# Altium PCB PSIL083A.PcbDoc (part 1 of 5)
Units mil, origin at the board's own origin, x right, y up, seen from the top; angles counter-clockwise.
Board outline 8750 x 2700 mil, 4 copper layers (Top Layer, Signal Layer 1, Signal Layer 2, Bottom Layer), stack 61.2 mil thick; 463 components, 395 nets, 2267 pads, 745 vias.
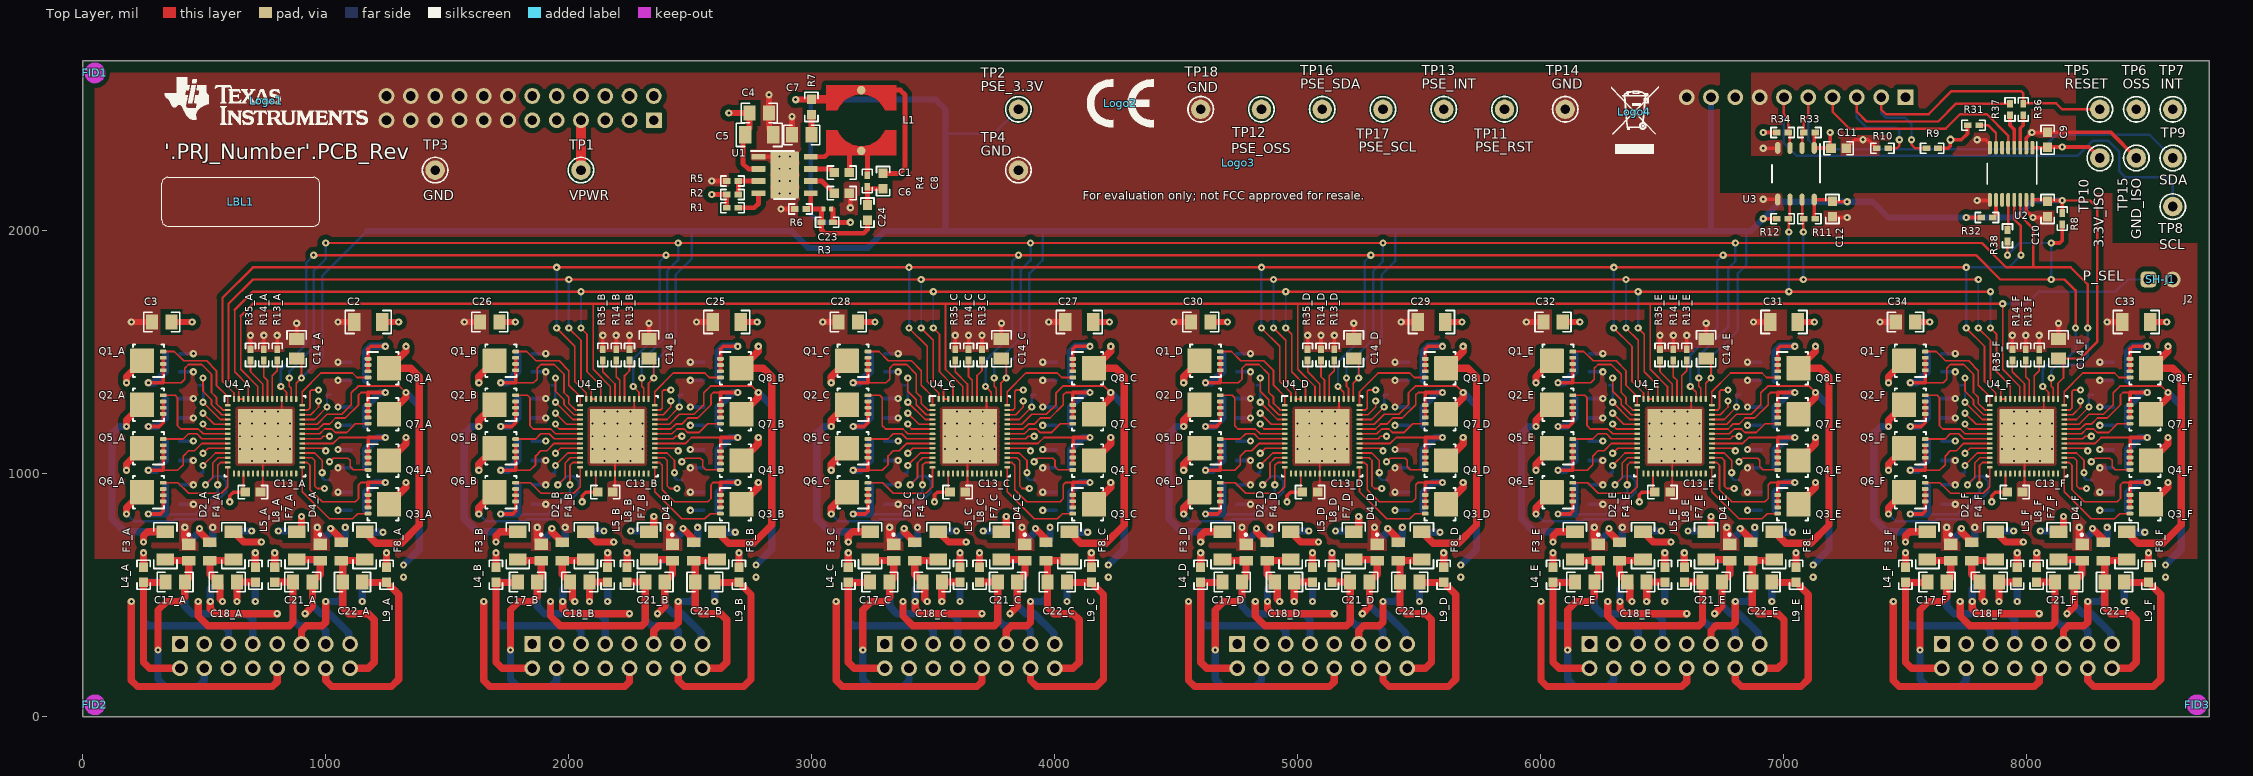
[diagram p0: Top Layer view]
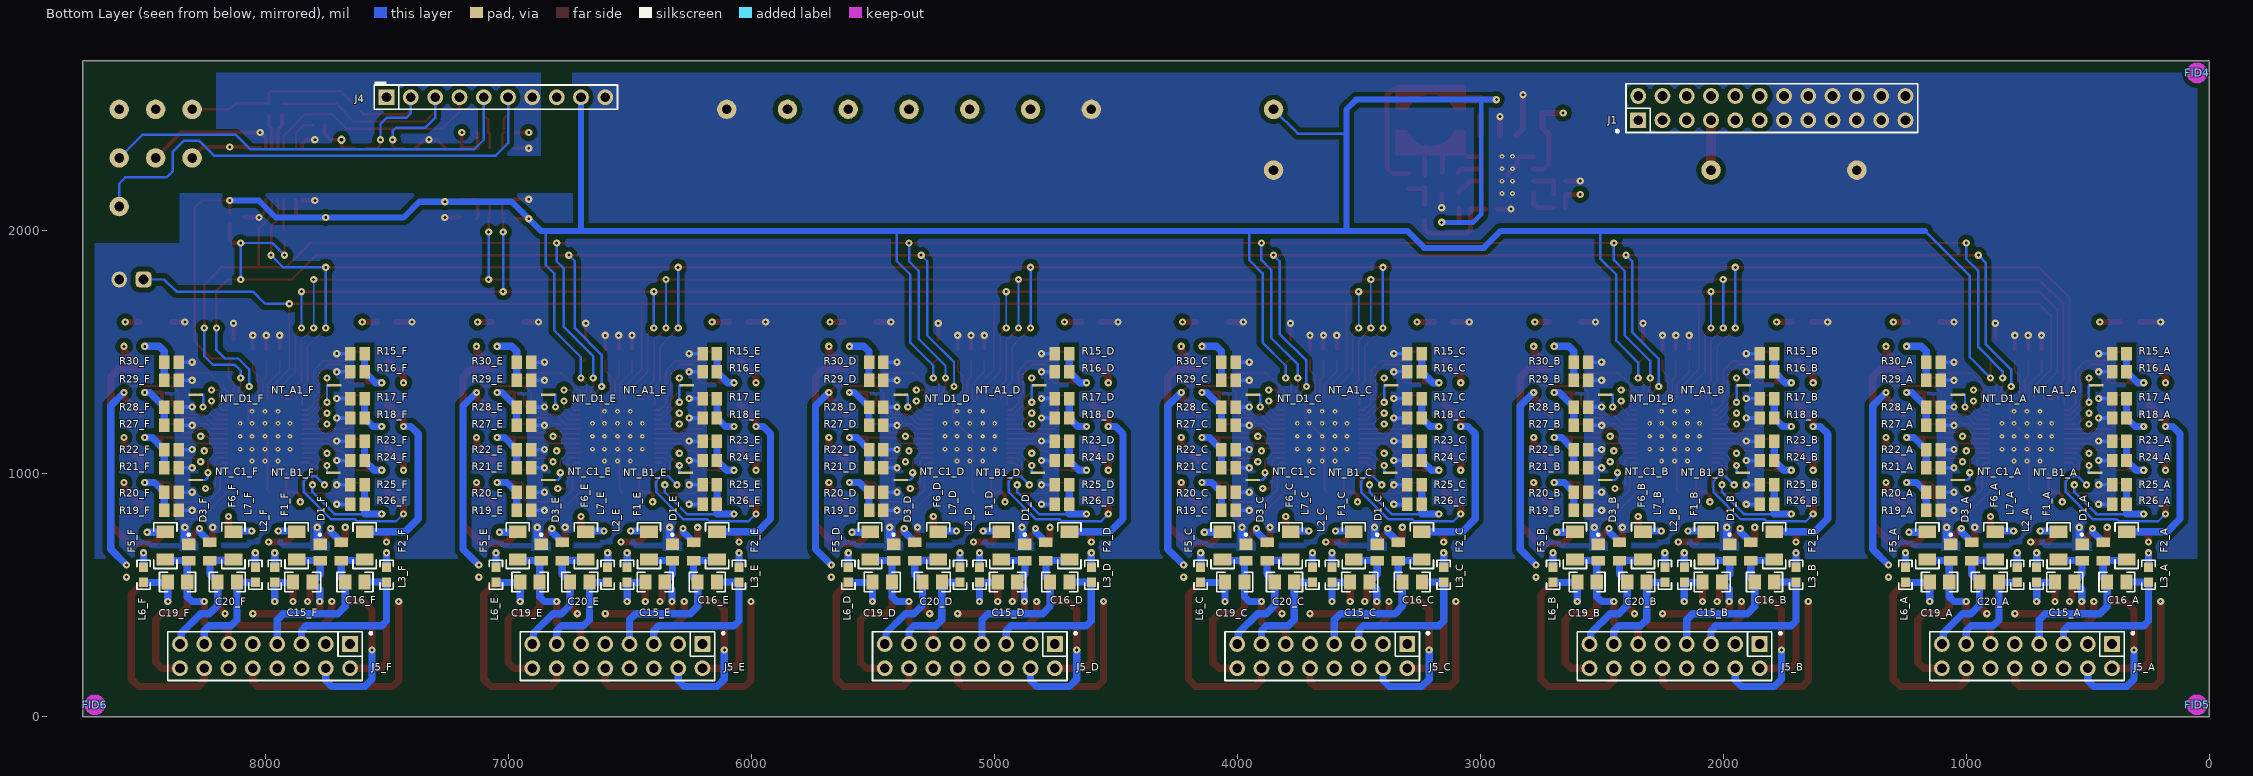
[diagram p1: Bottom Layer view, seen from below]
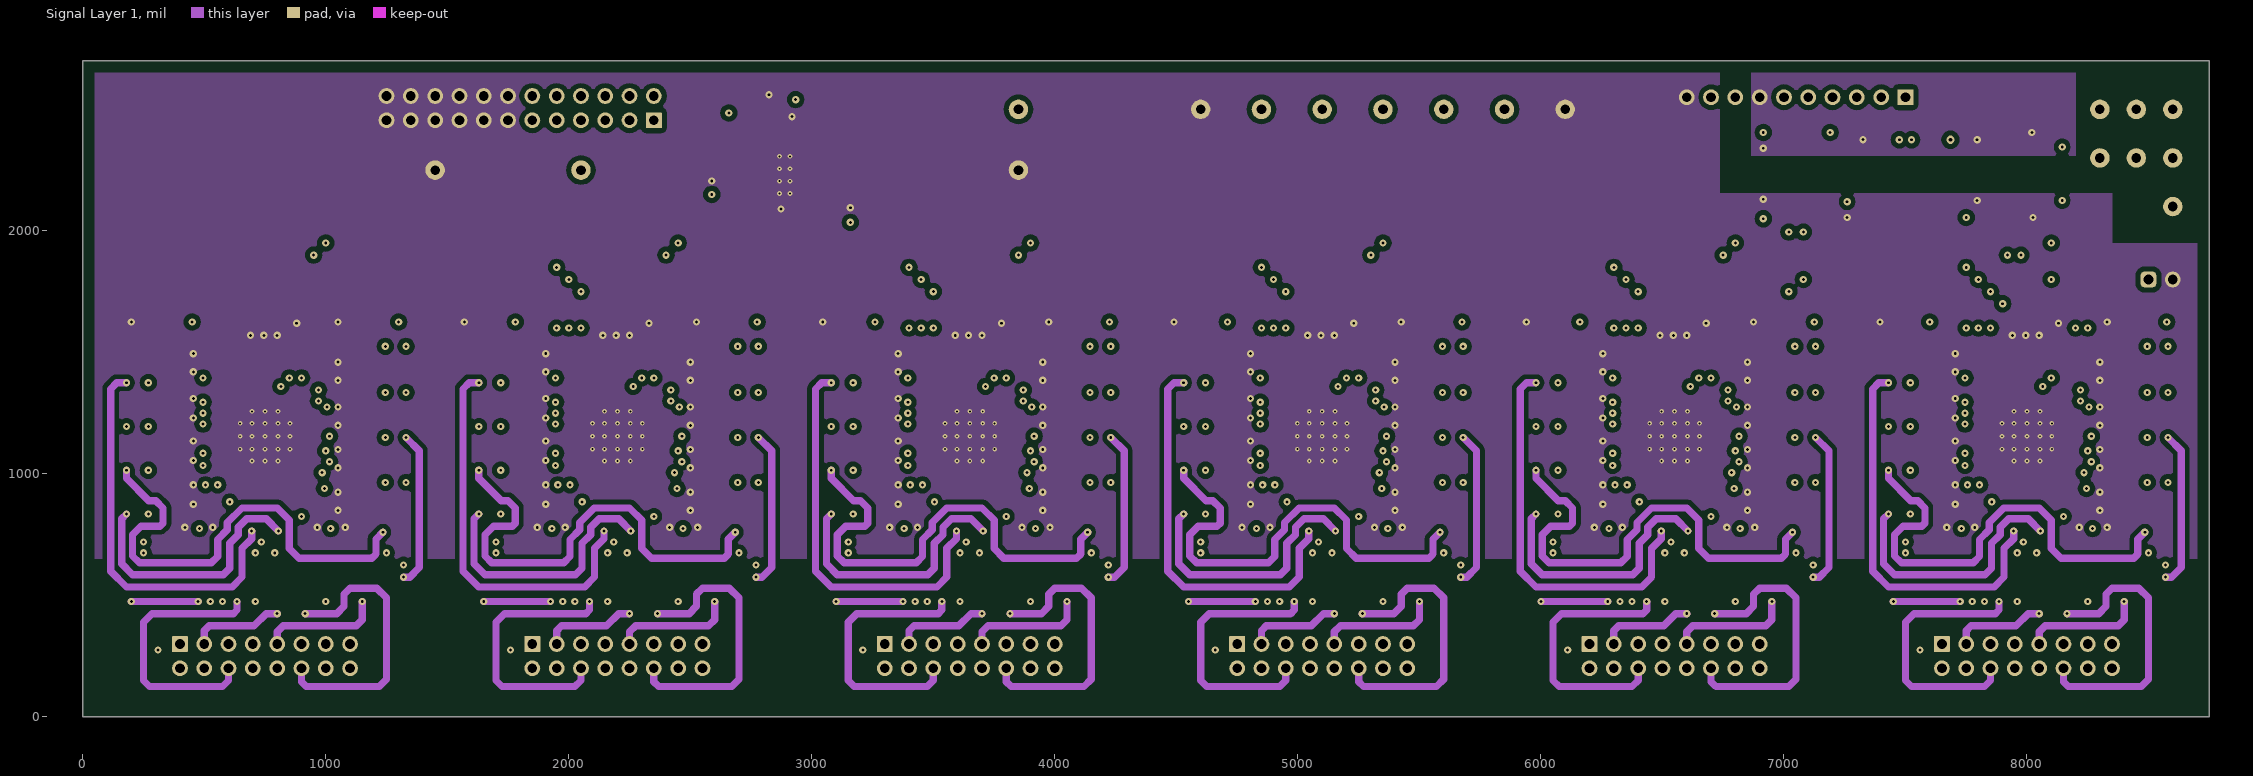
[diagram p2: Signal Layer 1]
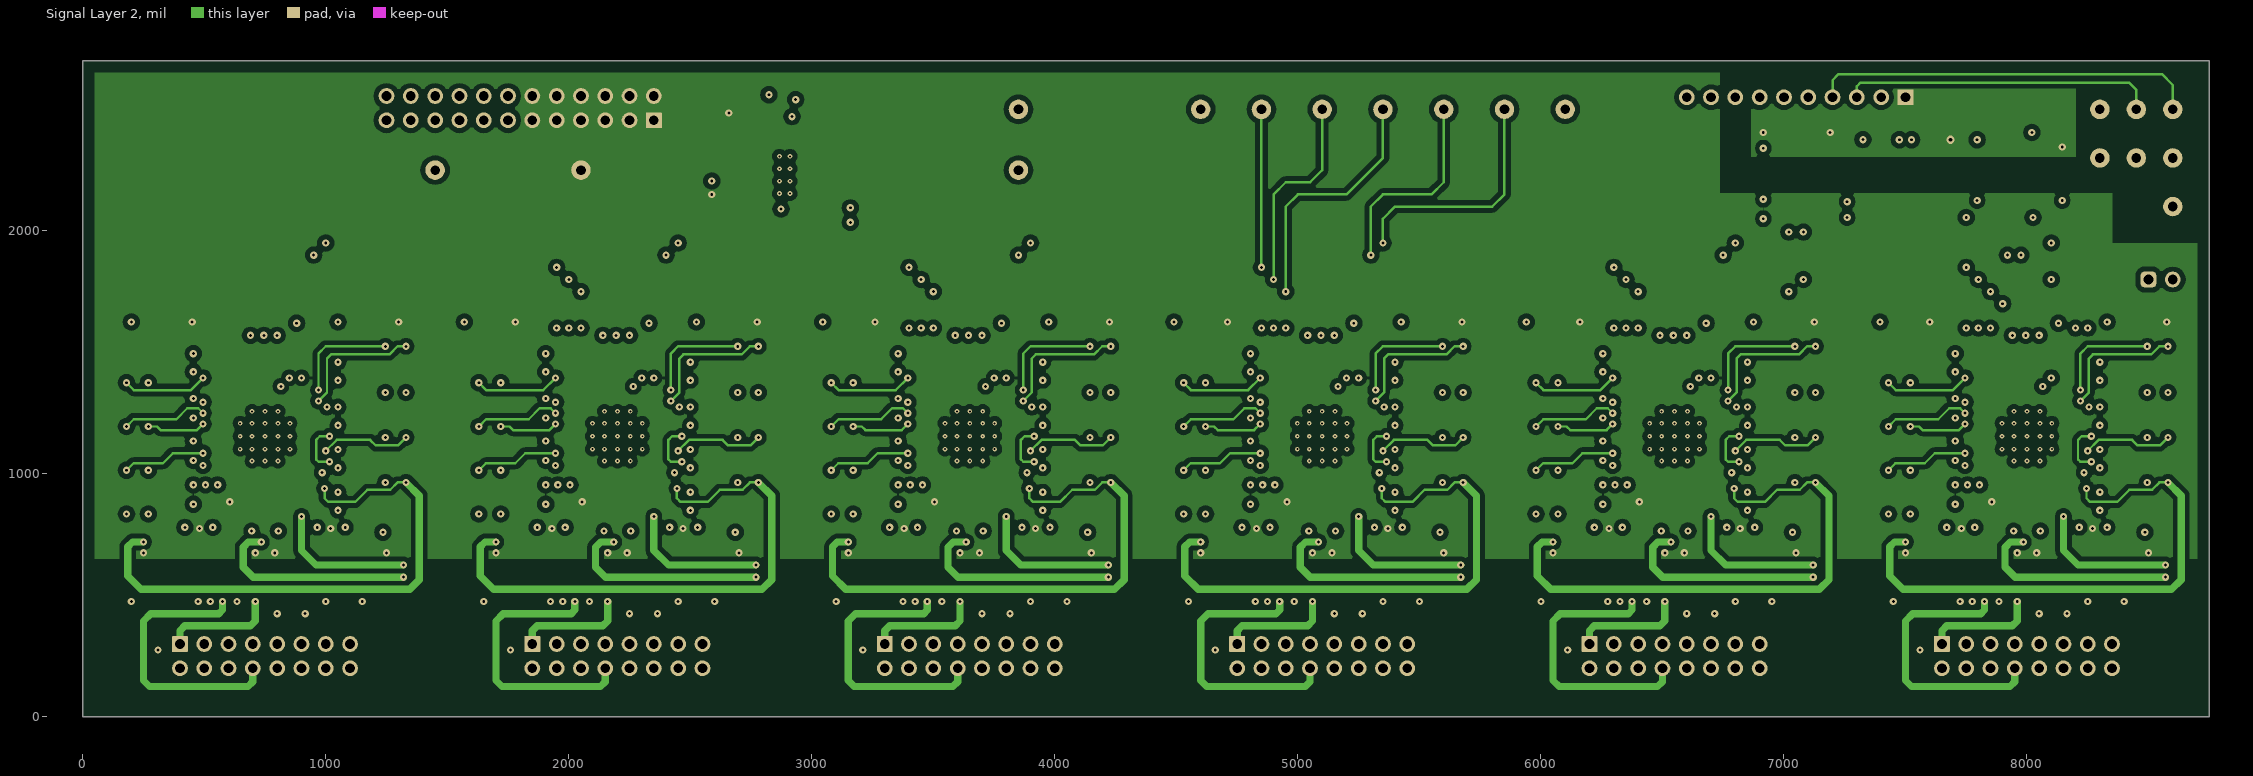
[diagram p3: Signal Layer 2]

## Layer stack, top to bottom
Top Solder: solder mask 0.4, Solder Resist, Dk 3.5
Top Layer: signal copper 2.8
Dielectric1: core 20, FR-4, Dk 4.2
Signal Layer 1: signal copper 2.8
Dielectric 2: prepreg 10, FR-4, Dk 4.2
Signal Layer 2: signal copper 2.8
Dielectric 3: core 20, FR-4, Dk 4.2
Bottom Layer: signal copper 2.8
Bottom Solder: solder mask 0.4, Solder Resist, Dk 3.5

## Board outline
0,0 8750,0 8750,2700 0,2700

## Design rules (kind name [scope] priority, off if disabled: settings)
AcuteAngle [All] p1: minimum=4.50000000000000E+0001 checktracksonly=FALSE
AssemblyTestPointUsage [All] p1: valid=2
BoardOutlineClearance BoardOutlineClearance_MountingHoles [OnCopper and InComponentClass('Mounting Holes')] p1: gap=40 ignorepadtopadclearanceinfootprint=FALSE
BoardOutlineClearance BoardOutlineClearance_Poly [OnCopper and IsPoly] p2: gap=25 ignorepadtopadclearanceinfootprint=FALSE
BoardOutlineClearance [OnCopper and Not InComponentClass('Logo') and not InComponentClass('FiducialMark') and not InRegion(1000,500,4000,800) and not InPoly] p3: gap=50 ignorepadtopadclearanceinfootprint=FALSE
Clearance Clearance_1 [InNamedPolygon('TOP_LAYER_PSE_S1_A_P004')] p1: gap=10 ignorepadtopadclearanceinfootprint=FALSE except(0: Arc-Hole Track-Hole SMDPad-Hole THPad-Hole Via-Hole Fill-Hole Poly-Hole Region-Hole Text-Hole)
Clearance Clearance_Keepouts [((IsTrack Or IsArc) And Not InPoly) And IsFree and IsKeepOut vs ((IsTrack Or IsArc) And Not InPoly) And IsFree and IsKeepOut] p2: gap=0 ignorepadtopadclearanceinfootprint=FALSE
Clearance Clearance_Poly [InPolygon] p3: gap=20 ignorepadtopadclearanceinfootprint=FALSE
Clearance Clearance_FiducialMark [IsKeepOut and InComponentClass('FiducialMark') vs IsPad and InComponentClass('FiducialMark')] p4: gap=0 ignorepadtopadclearanceinfootprint=FALSE
Clearance [All] p5: gap=7.87 ignorepadtopadclearanceinfootprint=FALSE except(0: Arc-Hole Track-Hole SMDPad-Hole THPad-Hole Via-Hole Fill-Hole Poly-Hole Region-Hole Text-Hole)
ComponentClearance ComponentClearance_MountingHoles_FiducialMarks [InComponentClass('Mounting Holes') vs InComponentClass('FiducialMark')] p1: gap=50 collisioncheckmode=3 verticalgap=10 showdistances=FALSE
ComponentClearance ComponentClearance_Shunt [InComponentClass('Header') vs InComponentClass('Shunt')] p2: gap=0 collisioncheckmode=3 verticalgap=0 showdistances=FALSE
ComponentClearance ComponentClearance_Logo [InComponentClass('Logo')] p3: gap=50 collisioncheckmode=3 verticalgap=10 showdistances=FALSE
ComponentClearance ComponentClearance_ScrewToNut [(HasFootprint('NY PMS 440 0025 PH')) vs (HasFootprint('Keystone_1902C'))] p4: gap=5 collisioncheckmode=3 verticalgap=10 showdistances=FALSE
ComponentClearance ComponentClearance_MountingHoles [InComponentClass('Mounting Holes')] p5: gap=250 collisioncheckmode=3 verticalgap=100000 showdistances=FALSE
ComponentClearance ComponentClearance_SmallPassives [HasFootprint('0201*') or HasFootprint('0402*') or HasFootprint('0508') or HasFootprint('0603*') or HasFootprint('0612') or HasFootprint('0805*') or HasFootprint('0815*') or HasFootprint('0830*') or HasFootprint('1206*') or HasFootprint('1210*') or HasFootprint('1808*') or HasFootprint('1812*') or HasFootprint('1825*') or HasFootprint('2010*') or HasFootprint('2220*') or HasFootprint('2225*') or HasFootprint('2512*') or HasFootprint('2728*') or HasFootprint('3518*') vs HasFootprint('0201*') or HasFootprint('0402*') or HasFootprint('0508') or HasFootprint('0603*') or HasFootprint('0612') or HasFootprint('0805*') or HasFootprint('0815*') or HasFootprint('0830*') or HasFootprint('1206*') or HasFootprint('1210*') or HasFootprint('1808*') or HasFootprint('1812*') or HasFootprint('1825*') or HasFootprint('2010*') or HasFootprint('2220*') or HasFootprint('2225*') or HasFootprint('2512*') or HasFootprint('2728*') or HasFootprint('3518*')] p6: gap=14.96 collisioncheckmode=3 verticalgap=10 showdistances=FALSE
ComponentClearance ComponentClearance_THtoSMT [IsThruComponent vs IsSMTComponent] p7: gap=40 collisioncheckmode=3 verticalgap=30 showdistances=FALSE
ComponentClearance ComponentClearance_THtoTH [IsThruComponent vs IsThruComponent] p8: gap=30 collisioncheckmode=3 verticalgap=30 showdistances=FALSE
ComponentClearance [All] p9: gap=30 collisioncheckmode=3 verticalgap=10 showdistances=FALSE
DiffPairsRouting [All] p1: maxlimit=100 minlimit=10 mostfreqgap=10 toplayer_minwidth=15 toplayer_maxwidth=15 toplayer_prefwidth=15 midlayer1_minwidth=15 midlayer1_maxwidth=15 midlayer1_prefwidth=15 midlayer2_minwidth=15 midlayer2_maxwidth=15 midlayer2_prefwidth=15 bottomlayer_minwidth=15 bottomlayer_maxwidth=15 bottomlayer_prefwidth=15 maxuncoupledlength=1000
FabricationTestPointUsage TestPointUsage [All] p1: valid=2 allowmultiple=FALSE
FabricationTestpoint Testpoint [All] p1: side=3 testpointundercomponent=TRUE minsize=40 maxsize=100 preferedsize=60 minholesize=0 maxholesize=40 preferedholesize=32 testpointgrid=1 allowsidetop=TRUE allowsidebottom=TRUE usegrid=TRUE gridtolerance=0.01
FanoutControl Fanout_LCC [IsLCC] p1: bgadir=Out bgaviamode=Centered fanoutstyle=Auto fanoutdirection=Alternating viagrid=1 // Fanout_LCC (Default Rule)
FanoutControl Fanout_BGA [IsBGA] p2: bgadir=Out bgaviamode=Centered fanoutstyle=Auto fanoutdirection=Alternating viagrid=1 // Fanout_BGA (Default Rule)
FanoutControl Fanout_Default [All] p4: bgadir=Out bgaviamode=Centered fanoutstyle=Auto fanoutdirection=Alternating viagrid=1 // Fanout_Default (Default Rule)
FanoutControl Fanout_Small [(CompPinCount < 5)] p5: bgadir=Out bgaviamode=Centered fanoutstyle=Auto fanoutdirection=OutThenIn viagrid=1 // Fanout_Small (Default Rule)
HoleSize [All] p1: absolutevalues=TRUE maxlimit=251 minlimit=7.87 maxpercent=80.000 minpercent=20.000
MinimumAnnularRing MinimumAnnularRing_ThermalPadVias [IsVia and InAnyComponent] p1: minimumring=5.91
MinimumAnnularRing [All] p2: minimumring=8
MinimumSolderMaskSliver MinimumSolderMaskSliver_Logo [InComponentClass('Logo') vs InComponentClass('Logo')] p1: minsoldermaskwidth=0.7
MinimumSolderMaskSliver [All] p2: minsoldermaskwidth=3.94
PlaneConnect [All] p1: planeconnectstyle=Relief reliefexpansion=10 reliefentries=4 reliefconductorwidth=10 reliefairgap=10
PolygonConnect [All] p1: connectstyle=Direct reliefconductorwidth=10 reliefentries=4 polygonreliefangle="90 Angle" airgapwidth=10
RoomDefinition A [InComponentClass('A')] p1: confinementstyle=ConfineIn formatcopy=TRUE lockcomponents=FALSE outline 50,1700 1450,1700 1450,50 50,50
RoomDefinition F [InComponentClass('F')] p2: confinementstyle=ConfineIn formatcopy=TRUE lockcomponents=FALSE outline 7300,1700 8700,1700 8700,50 7300,50
RoomDefinition E [InComponentClass('E')] p3: confinementstyle=ConfineIn formatcopy=TRUE lockcomponents=FALSE outline 5850,1700 7250,1700 7250,50 5850,50
RoomDefinition D [InComponentClass('D')] p4: confinementstyle=ConfineIn formatcopy=TRUE lockcomponents=FALSE outline 4400,1700 5800,1700 5800,50 4400,50
RoomDefinition C [InComponentClass('C')] p5: confinementstyle=ConfineIn formatcopy=TRUE lockcomponents=FALSE outline 2950,1700 4350,1700 4350,50 2950,50
RoomDefinition B [InComponentClass('B')] p6: confinementstyle=ConfineIn formatcopy=TRUE lockcomponents=FALSE outline 1500,1700 2900,1700 2900,50 1500,50
RoutingVias ThermalPadVias [IsVia and InAnyComponent] p1: holewidth=7.87 width=19.68 viastyle="Through Hole" minholewidth=7.87 minwidth=19.68 maxholewidth=12.99 maxwidth=23.62
RoutingVias [All] p2: holewidth=12 width=30 viastyle="Through Hole" minholewidth=7.87 minwidth=26 maxholewidth=40 maxwidth=65
SilkToBoardRegionClearance [Not ((IsComment or IsDesignator) And (Hide <> 'False')) and not InRegion(1000,500,4000,800)] p1:
SilkToSilkClearance SilkToSilkClearance_Pb-FreeLogo [(HasFootprint('Pb-Free_Overlay_Medium') OR HasFootprint('Pb-Free_Overlay_Small')) vs (HasFootprint('Pb-Free_Overlay_Medium') OR HasFootprint('Pb-Free_Overlay_Small'))] p1: silktosilkclearance=0
SilkToSilkClearance [All] p2: silktosilkclearance=4
SilkToSolderMaskClearance SilkToComponentPadClearance [(IsPad or IsFill or IsRegion) and InAnycomponent] p1: minsilkscreentomaskgap=5 clearancetoexposedcopper=TRUE
SilkToSolderMaskClearance "Silk to Solder Mask Opening" [All] p2: minsilkscreentomaskgap=4 clearancetoexposedcopper=FALSE
SolderMaskExpansion [All] p1: expansion=1.97
Width [All] p1: maxlimit=100 minlimit=6 preferedwidth=10 checkconnectedcopper=TRUE
15 further rules are at their usual default settings.

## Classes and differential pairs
component class U_PSIL083A_EVM_Hardware: !PCB FID1 FID2 FID3 FID4 FID5 FID6 LBL1 Logo1 Logo2 Logo3 Logo4 SH-J1 ZZ1 ZZ2 ZZ3 ZZ4 ZZ5
component class Shunt: SH-J1
component class Logo: Logo1
component class Label: LBL1
component class FiducialMark: FID1 FID2 FID3 FID4 FID5 FID6
component class AssemblyNote: ZZ1 ZZ2 ZZ3 ZZ4 ZZ5
component class A: C13_A C14_A C15_A C16_A C17_A C18_A C19_A C20_A C21_A C22_A D1_A D2_A D3_A D4_A F1_A F2_A F3_A F4_A F5_A F6_A F7_A F8_A J5_A L2_A L3_A L4_A L5_A L6_A L7_A L8_A L9_A NT_A1_A NT_B1_A NT_C1_A NT_D1_A Q1_A Q2_A Q3_A Q4_A Q5_A Q6_A Q7_A Q8_A R13_A R14_A R15_A R16_A R17_A R18_A R19_A R20_A R21_A R22_A R23_A R24_A R25_A R26_A R27_A R28_A R29_A R30_A R35_A U4_A
component class B: C13_B C14_B C15_B C16_B C17_B C18_B C19_B C20_B C21_B C22_B D1_B D2_B D3_B D4_B F1_B F2_B F3_B F4_B F5_B F6_B F7_B F8_B J5_B L2_B L3_B L4_B L5_B L6_B L7_B L8_B L9_B NT_A1_B NT_B1_B NT_C1_B NT_D1_B Q1_B Q2_B Q3_B Q4_B Q5_B Q6_B Q7_B Q8_B R13_B R14_B R15_B R16_B R17_B R18_B R19_B R20_B R21_B R22_B R23_B R24_B R25_B R26_B R27_B R28_B R29_B R30_B R35_B U4_B
component class C: C13_C C14_C C15_C C16_C C17_C C18_C C19_C C20_C C21_C C22_C D1_C D2_C D3_C D4_C F1_C F2_C F3_C F4_C F5_C F6_C F7_C F8_C J5_C L2_C L3_C L4_C L5_C L6_C L7_C L8_C L9_C NT_A1_C NT_B1_C NT_C1_C NT_D1_C Q1_C Q2_C Q3_C Q4_C Q5_C Q6_C Q7_C Q8_C R13_C R14_C R15_C R16_C R17_C R18_C R19_C R20_C R21_C R22_C R23_C R24_C R25_C R26_C R27_C R28_C R29_C R30_C R35_C U4_C
component class D: C13_D C14_D C15_D C16_D C17_D C18_D C19_D C20_D C21_D C22_D D1_D D2_D D3_D D4_D F1_D F2_D F3_D F4_D F5_D F6_D F7_D F8_D J5_D L2_D L3_D L4_D L5_D L6_D L7_D L8_D L9_D NT_A1_D NT_B1_D NT_C1_D NT_D1_D Q1_D Q2_D Q3_D Q4_D Q5_D Q6_D Q7_D Q8_D R13_D R14_D R15_D R16_D R17_D R18_D R19_D R20_D R21_D R22_D R23_D R24_D R25_D R26_D R27_D R28_D R29_D R30_D R35_D U4_D
component class E: C13_E C14_E C15_E C16_E C17_E C18_E C19_E C20_E C21_E C22_E D1_E D2_E D3_E D4_E F1_E F2_E F3_E F4_E F5_E F6_E F7_E F8_E J5_E L2_E L3_E L4_E L5_E L6_E L7_E L8_E L9_E NT_A1_E NT_B1_E NT_C1_E NT_D1_E Q1_E Q2_E Q3_E Q4_E Q5_E Q6_E Q7_E Q8_E R13_E R14_E R15_E R16_E R17_E R18_E R19_E R20_E R21_E R22_E R23_E R24_E R25_E R26_E R27_E R28_E R29_E R30_E R35_E U4_E
component class F: C13_F C14_F C15_F C16_F C17_F C18_F C19_F C20_F C21_F C22_F D1_F D2_F D3_F D4_F F1_F F2_F F3_F F4_F F5_F F6_F F7_F F8_F J5_F L2_F L3_F L4_F L5_F L6_F L7_F L8_F L9_F NT_A1_F NT_B1_F NT_C1_F NT_D1_F Q1_F Q2_F Q3_F Q4_F Q5_F Q6_F Q7_F Q8_F R13_F R14_F R15_F R16_F R17_F R18_F R19_F R20_F R21_F R22_F R23_F R24_F R25_F R26_F R27_F R28_F R29_F R30_F R35_F U4_F
component class Header: J1 J2 J4 J5_A J5_B J5_C J5_D J5_E J5_F
component class PSIL083A_SH1: C1 C2 C3 C4 C5 C6 C7 C8 C9 C10 C11 C12 C23 C24 C25 C26 C27 C28 C29 C30 C31 C32 C33 C34 J1 J2 J4 L1 R1 R2 R3 R4 R5 R6 R7 R8 R9 R10 R11 R12 R31 R32 R33 R34 R36 R37 R38 TP1 TP2 TP3 TP4 TP5 TP6 TP7 TP8 TP9 TP10 TP11 TP12 TP13 TP14 TP15 TP16 TP17 TP18 U1 U2 U3
channel class PSIL083A_SH2: A B C D E F

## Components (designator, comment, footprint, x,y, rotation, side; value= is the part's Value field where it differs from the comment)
C1 "885012206089" 0603 3123.31,2240 r180 top value=0.01uF
C2 "GCJ31CR72A105KA01K" 1206 1175,1625 r0 top value=1uF
C3 "C2012X7R2A104K125AA" 0805_HV 325,1625 r0 top value=0.1uF
C4 "C2012X7R2A104K125AA" 0805_HV 2783.31,2485 r180 top value=0.1uF
C5 "GCJ31CR72A105KA01K" 1206 2783.31,2395 r180 top value=1uF
C6 "CL10B105MO8NNWC" 0603 3123.31,2155 r0 top value=1uF
C7 "885012207026" 0805_HV 2958.31,2395 r180 top value=10uF
C8 "GRM1885C1H332JA01D" 0603 3293.31,2205 r270 top value=3300pF
C9 "885012206095" 0603 8085,2375 r90 top value=0.1uF
C10 "885012206095" 0603 8085,2090 r270 top value=0.1uF
C11 "885012206095" 0603 7225,2340 r0 top value=0.1uF
C12 "885012206095" 0603 7199.69,2090 r270 top value=0.1uF
C13_A "CGA3E3X7S2A104K080AB" 0603 700,925 r0 top value=0.1uF (schematic designator C13)
C13_B "CGA3E3X7S2A104K080AB" 0603 2150,925 r0 top value=0.1uF (schematic designator C13)
C13_C "CGA3E3X7S2A104K080AB" 0603 3600,925 r0 top value=0.1uF (schematic designator C13)
C13_D "CGA3E3X7S2A104K080AB" 0603 5050,925 r0 top value=0.1uF (schematic designator C13)
C13_E "CGA3E3X7S2A104K080AB" 0603 6500,925 r0 top value=0.1uF (schematic designator C13)
C13_F "CGA3E3X7S2A104K080AB" 0603 7950,925 r0 top value=0.1uF (schematic designator C13)
C14_A "C0805C104K4RACTU" 0805_HV 880,1515 r90 top value=0.1uF (schematic designator C14)
C14_B "C0805C104K4RACTU" 0805_HV 2330,1515 r90 top value=0.1uF (schematic designator C14)
C14_C "C0805C104K4RACTU" 0805_HV 3780,1515 r90 top value=0.1uF (schematic designator C14)
C14_D "C0805C104K4RACTU" 0805_HV 5230,1515 r90 top value=0.1uF (schematic designator C14)
C14_E "C0805C104K4RACTU" 0805_HV 6680,1515 r90 top value=0.1uF (schematic designator C14)
C14_F "C0805C104K4RACTU" 0805_HV 8130,1515 r90 top value=0.1uF (schematic designator C14)
C15_A "C2012X7R2A104K125AA" 0805_HV 595,555 r180 bottom value=0.1uF (schematic designator C15)
C15_B "C2012X7R2A104K125AA" 0805_HV 2045,555 r180 bottom value=0.1uF (schematic designator C15)
C15_C "C2012X7R2A104K125AA" 0805_HV 3495,555 r180 bottom value=0.1uF (schematic designator C15)
C15_D "C2012X7R2A104K125AA" 0805_HV 4945,555 r180 bottom value=0.1uF (schematic designator C15)
C15_E "C2012X7R2A104K125AA" 0805_HV 6395,555 r180 bottom value=0.1uF (schematic designator C15)
C15_F "C2012X7R2A104K125AA" 0805_HV 7845,555 r180 bottom value=0.1uF (schematic designator C15)
C16_A "C2012X7R2A104K125AA" 0805_HV 380,555 r0 bottom value=0.1uF (schematic designator C16)
C16_B "C2012X7R2A104K125AA" 0805_HV 1830,555 r0 bottom value=0.1uF (schematic designator C16)
C16_C "C2012X7R2A104K125AA" 0805_HV 3280,555 r0 bottom value=0.1uF (schematic designator C16)
C16_D "C2012X7R2A104K125AA" 0805_HV 4730,555 r0 bottom value=0.1uF (schematic designator C16)
C16_E "C2012X7R2A104K125AA" 0805_HV 6180,555 r0 bottom value=0.1uF (schematic designator C16)
C16_F "C2012X7R2A104K125AA" 0805_HV 7630,555 r0 bottom value=0.1uF (schematic designator C16)
C17_A "C2012X7R2A104K125AA" 0805_HV 380,555 r0 top value=0.1uF (schematic designator C17)
C17_B "C2012X7R2A104K125AA" 0805_HV 1830,555 r0 top value=0.1uF (schematic designator C17)
C17_C "C2012X7R2A104K125AA" 0805_HV 3280,555 r0 top value=0.1uF (schematic designator C17)
C17_D "C2012X7R2A104K125AA" 0805_HV 4730,555 r0 top value=0.1uF (schematic designator C17)
C17_E "C2012X7R2A104K125AA" 0805_HV 6180,555 r0 top value=0.1uF (schematic designator C17)
C17_F "C2012X7R2A104K125AA" 0805_HV 7630,555 r0 top value=0.1uF (schematic designator C17)
C18_A "C2012X7R2A104K125AA" 0805_HV 595,555 r180 top value=0.1uF (schematic designator C18)
C18_B "C2012X7R2A104K125AA" 0805_HV 2045,555 r180 top value=0.1uF (schematic designator C18)
C18_C "C2012X7R2A104K125AA" 0805_HV 3495,555 r180 top value=0.1uF (schematic designator C18)
C18_D "C2012X7R2A104K125AA" 0805_HV 4945,555 r180 top value=0.1uF (schematic designator C18)
C18_E "C2012X7R2A104K125AA" 0805_HV 6395,555 r180 top value=0.1uF (schematic designator C18)
C18_F "C2012X7R2A104K125AA" 0805_HV 7845,555 r180 top value=0.1uF (schematic designator C18)
C19_A "C2012X7R2A104K125AA" 0805_HV 1110,555 r180 bottom value=0.1uF (schematic designator C19)
C19_B "C2012X7R2A104K125AA" 0805_HV 2560,555 r180 bottom value=0.1uF (schematic designator C19)
C19_C "C2012X7R2A104K125AA" 0805_HV 4010,555 r180 bottom value=0.1uF (schematic designator C19)
C19_D "C2012X7R2A104K125AA" 0805_HV 5460,555 r180 bottom value=0.1uF (schematic designator C19)
C19_E "C2012X7R2A104K125AA" 0805_HV 6910,555 r180 bottom value=0.1uF (schematic designator C19)
C19_F "C2012X7R2A104K125AA" 0805_HV 8360,555 r180 bottom value=0.1uF (schematic designator C19)
C20_A "C2012X7R2A104K125AA" 0805_HV 905,555 r0 bottom value=0.1uF (schematic designator C20)
C20_B "C2012X7R2A104K125AA" 0805_HV 2355,555 r0 bottom value=0.1uF (schematic designator C20)
C20_C "C2012X7R2A104K125AA" 0805_HV 3805,555 r0 bottom value=0.1uF (schematic designator C20)
C20_D "C2012X7R2A104K125AA" 0805_HV 5255,555 r0 bottom value=0.1uF (schematic designator C20)
C20_E "C2012X7R2A104K125AA" 0805_HV 6705,555 r0 bottom value=0.1uF (schematic designator C20)
C20_F "C2012X7R2A104K125AA" 0805_HV 8155,555 r0 bottom value=0.1uF (schematic designator C20)
C21_A "C2012X7R2A104K125AA" 0805_HV 905,555 r0 top value=0.1uF (schematic designator C21)
C21_B "C2012X7R2A104K125AA" 0805_HV 2355,555 r0 top value=0.1uF (schematic designator C21)
C21_C "C2012X7R2A104K125AA" 0805_HV 3805,555 r0 top value=0.1uF (schematic designator C21)
C21_D "C2012X7R2A104K125AA" 0805_HV 5255,555 r0 top value=0.1uF (schematic designator C21)
C21_E "C2012X7R2A104K125AA" 0805_HV 6705,555 r0 top value=0.1uF (schematic designator C21)
C21_F "C2012X7R2A104K125AA" 0805_HV 8155,555 r0 top value=0.1uF (schematic designator C21)
C22_A "C2012X7R2A104K125AA" 0805_HV 1110,555 r180 top value=0.1uF (schematic designator C22)
C22_B "C2012X7R2A104K125AA" 0805_HV 2560,555 r180 top value=0.1uF (schematic designator C22)
C22_C "C2012X7R2A104K125AA" 0805_HV 4010,555 r180 top value=0.1uF (schematic designator C22)
C22_D "C2012X7R2A104K125AA" 0805_HV 5460,555 r180 top value=0.1uF (schematic designator C22)
C22_E "C2012X7R2A104K125AA" 0805_HV 6910,555 r180 top value=0.1uF (schematic designator C22)
C22_F "C2012X7R2A104K125AA" 0805_HV 8360,555 r180 top value=0.1uF (schematic designator C22)
C23 "GCM1555C1H121FA16D" FP-GCM1555C1H121FA16D_0402-MFG 3063.31,2090 r180 top
C24 "885012206095" 0603 3228.31,2075 r270 top value=0.1uF
C25 "GCJ31CR72A105KA01K" 1206 2650,1625 r0 top value=1uF
C26 "C2012X7R2A104K125AA" 0805_HV 1675,1625 r0 top value=0.1uF
C27 "GCJ31CR72A105KA01K" 1206 4100,1625 r0 top value=1uF
C28 "C2012X7R2A104K125AA" 0805_HV 3150,1625 r0 top value=0.1uF
C29 "GCJ31CR72A105KA01K" 1206 5550,1625 r0 top value=1uF
C30 "C2012X7R2A104K125AA" 0805_HV 4600,1625 r0 top value=0.1uF
C31 "GCJ31CR72A105KA01K" 1206 7000,1625 r0 top value=1uF
C32 "C2012X7R2A104K125AA" 0805_HV 6050,1625 r0 top value=0.1uF
C33 "GCJ31CR72A105KA01K" 1206 8450,1625 r0 top value=1uF
C34 "C2012X7R2A104K125AA" 0805_HV 7500,1625 r0 top value=0.1uF
D1_A "CD143A-SR70" SOT-143-4 480,675 r180 bottom value=7V (schematic designator D1)
D1_B "CD143A-SR70" SOT-143-4 1930,675 r180 bottom value=7V (schematic designator D1)
D1_C "CD143A-SR70" SOT-143-4 3380,675 r180 bottom value=7V (schematic designator D1)
D1_D "CD143A-SR70" SOT-143-4 4830,675 r180 bottom value=7V (schematic designator D1)
D1_E "CD143A-SR70" SOT-143-4 6280,675 r180 bottom value=7V (schematic designator D1)
D1_F "CD143A-SR70" SOT-143-4 7730,675 r180 bottom value=7V (schematic designator D1)
D2_A "CD143A-SR70" SOT-143-4 480,675 r0 top value=7V (schematic designator D2)
D2_B "CD143A-SR70" SOT-143-4 1930,675 r0 top value=7V (schematic designator D2)
D2_C "CD143A-SR70" SOT-143-4 3380,675 r0 top value=7V (schematic designator D2)
D2_D "CD143A-SR70" SOT-143-4 4830,675 r0 top value=7V (schematic designator D2)
D2_E "CD143A-SR70" SOT-143-4 6280,675 r0 top value=7V (schematic designator D2)
D2_F "CD143A-SR70" SOT-143-4 7730,675 r0 top value=7V (schematic designator D2)
D3_A "CD143A-SR70" SOT-143-4 1020,675 r180 bottom value=7V (schematic designator D3)
D3_B "CD143A-SR70" SOT-143-4 2470,675 r180 bottom value=7V (schematic designator D3)
D3_C "CD143A-SR70" SOT-143-4 3920,675 r180 bottom value=7V (schematic designator D3)
D3_D "CD143A-SR70" SOT-143-4 5370,675 r180 bottom value=7V (schematic designator D3)
D3_E "CD143A-SR70" SOT-143-4 6820,675 r180 bottom value=7V (schematic designator D3)
D3_F "CD143A-SR70" SOT-143-4 8270,675 r180 bottom value=7V (schematic designator D3)
D4_A "CD143A-SR70" SOT-143-4 1020,675 r0 top value=7V (schematic designator D4)
D4_B "CD143A-SR70" SOT-143-4 2470,675 r0 top value=7V (schematic designator D4)
D4_C "CD143A-SR70" SOT-143-4 3920,675 r0 top value=7V (schematic designator D4)
D4_D "CD143A-SR70" SOT-143-4 5370,675 r0 top value=7V (schematic designator D4)
D4_E "CD143A-SR70" SOT-143-4 6820,675 r0 top value=7V (schematic designator D4)
D4_F "CD143A-SR70" SOT-143-4 8270,675 r0 top value=7V (schematic designator D4)
F1_A "C1S 1.5A" 1206 620,705 r90 bottom (schematic designator F1)
F1_B "C1S 1.5A" 1206 2070,705 r90 bottom (schematic designator F1)
F1_C "C1S 1.5A" 1206 3520,705 r90 bottom (schematic designator F1)
F1_D "C1S 1.5A" 1206 4970,705 r90 bottom (schematic designator F1)
F1_E "C1S 1.5A" 1206 6420,705 r90 bottom (schematic designator F1)
F1_F "C1S 1.5A" 1206 7870,705 r90 bottom (schematic designator F1)
F2_A "C1S 1.5A" 1206 340,705 r90 bottom (schematic designator F2)
F2_B "C1S 1.5A" 1206 1790,705 r90 bottom (schematic designator F2)
F2_C "C1S 1.5A" 1206 3240,705 r90 bottom (schematic designator F2)
F2_D "C1S 1.5A" 1206 4690,705 r90 bottom (schematic designator F2)
F2_E "C1S 1.5A" 1206 6140,705 r90 bottom (schematic designator F2)
F2_F "C1S 1.5A" 1206 7590,705 r90 bottom (schematic designator F2)
F3_A "C1S 1.5A" 1206 340,705 r90 top (schematic designator F3)
F3_B "C1S 1.5A" 1206 1790,705 r90 top (schematic designator F3)
F3_C "C1S 1.5A" 1206 3240,705 r90 top (schematic designator F3)
F3_D "C1S 1.5A" 1206 4690,705 r90 top (schematic designator F3)
F3_E "C1S 1.5A" 1206 6140,705 r90 top (schematic designator F3)
F3_F "C1S 1.5A" 1206 7590,705 r90 top (schematic designator F3)
F4_A "C1S 1.5" 1206 620,705 r90 top (schematic designator F4)
F4_B "C1S 1.5" 1206 2070,705 r90 top (schematic designator F4)
F4_C "C1S 1.5" 1206 3520,705 r90 top (schematic designator F4)
F4_D "C1S 1.5" 1206 4970,705 r90 top (schematic designator F4)
F4_E "C1S 1.5" 1206 6420,705 r90 top (schematic designator F4)
F4_F "C1S 1.5" 1206 7870,705 r90 top (schematic designator F4)
F5_A "C1S 1.5A" 1206 1160,705 r90 bottom (schematic designator F5)
F5_B "C1S 1.5A" 1206 2610,705 r90 bottom (schematic designator F5)
F5_C "C1S 1.5A" 1206 4060,705 r90 bottom (schematic designator F5)
F5_D "C1S 1.5A" 1206 5510,705 r90 bottom (schematic designator F5)
F5_E "C1S 1.5A" 1206 6960,705 r90 bottom (schematic designator F5)
F5_F "C1S 1.5A" 1206 8410,705 r90 bottom (schematic designator F5)
F6_A "C1S 1.5A" 1206 880,705 r90 bottom (schematic designator F6)
F6_B "C1S 1.5A" 1206 2330,705 r90 bottom (schematic designator F6)
F6_C "C1S 1.5A" 1206 3780,705 r90 bottom (schematic designator F6)
F6_D "C1S 1.5A" 1206 5230,705 r90 bottom (schematic designator F6)
F6_E "C1S 1.5A" 1206 6680,705 r90 bottom (schematic designator F6)
F6_F "C1S 1.5A" 1206 8130,705 r90 bottom (schematic designator F6)
F7_A "C1S 1.5A" 1206 880,705 r90 top (schematic designator F7)
F7_B "C1S 1.5A" 1206 2330,705 r90 top (schematic designator F7)
F7_C "C1S 1.5A" 1206 3780,705 r90 top (schematic designator F7)
F7_D "C1S 1.5A" 1206 5230,705 r90 top (schematic designator F7)
F7_E "C1S 1.5A" 1206 6680,705 r90 top (schematic designator F7)
F7_F "C1S 1.5A" 1206 8130,705 r90 top (schematic designator F7)
F8_A "C1S 1.5A" 1206 1160,705 r90 top (schematic designator F8)
F8_B "C1S 1.5A" 1206 2610,705 r90 top (schematic designator F8)
F8_C "C1S 1.5A" 1206 4060,705 r90 top (schematic designator F8)
F8_D "C1S 1.5A" 1206 5510,705 r90 top (schematic designator F8)
F8_E "C1S 1.5A" 1206 6960,705 r90 top (schematic designator F8)
F8_F "C1S 1.5A" 1206 8410,705 r90 top (schematic designator F8)
FID1 "Fiducial" Fiducial10-20 50,2650 r90 top
FID2 "Fiducial" Fiducial10-20 50,50 r90 top
FID3 "Fiducial" Fiducial10-20 8700,50 r90 top
FID4 "Fiducial" Fiducial10-20 50,2650 r90 bottom
FID5 "Fiducial" Fiducial10-20 50,50 r90 bottom
FID6 "Fiducial" Fiducial10-20 8700,50 r90 bottom
J1 "TSW-112-07-G-D" TSW-112-07-G-D 1800,2505 r180 bottom
J2 "TSW-102-07-G-S" TSW-102-07-G-S 8550,1800 r0 top
J4 "TSW-110-07-G-S" TSW-110-07-G-S 7050,2550 r180 bottom
J5_A "TSW-108-09-G-D" TSW-108-07-G-D 750,250 r0 bottom (schematic designator J5)
J5_B "TSW-108-09-G-D" TSW-108-07-G-D 2200,250 r0 bottom (schematic designator J5)
J5_C "TSW-108-09-G-D" TSW-108-07-G-D 3650,250 r0 bottom (schematic designator J5)
J5_D "TSW-108-09-G-D" TSW-108-07-G-D 5100,250 r0 bottom (schematic designator J5)
J5_E "TSW-108-09-G-D" TSW-108-07-G-D 6550,250 r0 bottom (schematic designator J5)
J5_F "TSW-108-09-G-D" TSW-108-07-G-D 8000,250 r0 bottom (schematic designator J5)
L1 "744062151" WE-TPC_6823 3203.31,2455 r180 top value=150uH
L2_A "MPZ1608S601ATD25" 0603 710,585 r270 bottom value="600 ohm" (schematic designator L2)
L2_B "MPZ1608S601ATD25" 0603 2160,585 r270 bottom value="600 ohm" (schematic designator L2)
L2_C "MPZ1608S601ATD25" 0603 3610,585 r270 bottom value="600 ohm" (schematic designator L2)
L2_D "MPZ1608S601ATD25" 0603 5060,585 r270 bottom value="600 ohm" (schematic designator L2)
L2_E "MPZ1608S601ATD25" 0603 6510,585 r270 bottom value="600 ohm" (schematic designator L2)
L2_F "MPZ1608S601ATD25" 0603 7960,585 r270 bottom value="600 ohm" (schematic designator L2)
L3_A "MPZ1608S601ATD25" 0603 250,585 r270 bottom value="600 ohm" (schematic designator L3)
L3_B "MPZ1608S601ATD25" 0603 1700,585 r270 bottom value="600 ohm" (schematic designator L3)
L3_C "MPZ1608S601ATD25" 0603 3150,585 r270 bottom value="600 ohm" (schematic designator L3)
L3_D "MPZ1608S601ATD25" 0603 4600,585 r270 bottom value="600 ohm" (schematic designator L3)
L3_E "MPZ1608S601ATD25" 0603 6050,585 r270 bottom value="600 ohm" (schematic designator L3)
L3_F "MPZ1608S601ATD25" 0603 7500,585 r270 bottom value="600 ohm" (schematic designator L3)
L4_A "MPZ1608S601ATD25" 0603 250,585 r270 top value="600 ohm" (schematic designator L4)
L4_B "MPZ1608S601ATD25" 0603 1700,585 r270 top value="600 ohm" (schematic designator L4)
L4_C "MPZ1608S601ATD25" 0603 3150,585 r270 top value="600 ohm" (schematic designator L4)
L4_D "MPZ1608S601ATD25" 0603 4600,585 r270 top value="600 ohm" (schematic designator L4)
L4_E "MPZ1608S601ATD25" 0603 6050,585 r270 top value="600 ohm" (schematic designator L4)
L4_F "MPZ1608S601ATD25" 0603 7500,585 r270 top value="600 ohm" (schematic designator L4)
L5_A "MPZ1608S601ATD25" 0603 710,585 r270 top value="600 ohm" (schematic designator L5)
L5_B "MPZ1608S601ATD25" 0603 2160,585 r270 top value="600 ohm" (schematic designator L5)
L5_C "MPZ1608S601ATD25" 0603 3610,585 r270 top value="600 ohm" (schematic designator L5)
L5_D "MPZ1608S601ATD25" 0603 5060,585 r270 top value="600 ohm" (schematic designator L5)
L5_E "MPZ1608S601ATD25" 0603 6510,585 r270 top value="600 ohm" (schematic designator L5)
L5_F "MPZ1608S601ATD25" 0603 7960,585 r270 top value="600 ohm" (schematic designator L5)
L6_A "MPZ1608S601ATD25" 0603 1250,585 r270 bottom value="600 ohm" (schematic designator L6)
L6_B "MPZ1608S601ATD25" 0603 2700,585 r270 bottom value="600 ohm" (schematic designator L6)
L6_C "MPZ1608S601ATD25" 0603 4150,585 r270 bottom value="600 ohm" (schematic designator L6)
L6_D "MPZ1608S601ATD25" 0603 5600,585 r270 bottom value="600 ohm" (schematic designator L6)
L6_E "MPZ1608S601ATD25" 0603 7050,585 r270 bottom value="600 ohm" (schematic designator L6)
L6_F "MPZ1608S601ATD25" 0603 8500,585 r270 bottom value="600 ohm" (schematic designator L6)
L7_A "MPZ1608S601ATD25" 0603 790,585 r270 bottom value="600 ohm" (schematic designator L7)
L7_B "MPZ1608S601ATD25" 0603 2240,585 r270 bottom value="600 ohm" (schematic designator L7)
L7_C "MPZ1608S601ATD25" 0603 3690,585 r270 bottom value="600 ohm" (schematic designator L7)
L7_D "MPZ1608S601ATD25" 0603 5140,585 r270 bottom value="600 ohm" (schematic designator L7)
L7_E "MPZ1608S601ATD25" 0603 6590,585 r270 bottom value="600 ohm" (schematic designator L7)
L7_F "MPZ1608S601ATD25" 0603 8040,585 r270 bottom value="600 ohm" (schematic designator L7)
L8_A "MPZ1608S601ATD25" 0603 790,585 r270 top value="600 ohm" (schematic designator L8)
L8_B "MPZ1608S601ATD25" 0603 2240,585 r270 top value="600 ohm" (schematic designator L8)
L8_C "MPZ1608S601ATD25" 0603 3690,585 r270 top value="600 ohm" (schematic designator L8)
L8_D "MPZ1608S601ATD25" 0603 5140,585 r270 top value="600 ohm" (schematic designator L8)
L8_E "MPZ1608S601ATD25" 0603 6590,585 r270 top value="600 ohm" (schematic designator L8)
L8_F "MPZ1608S601ATD25" 0603 8040,585 r270 top value="600 ohm" (schematic designator L8)
L9_A "MPZ1608S601ATD25" 0603 1250,585 r270 top value="600 ohm" (schematic designator L9)
L9_B "MPZ1608S601ATD25" 0603 2700,585 r270 top value="600 ohm" (schematic designator L9)
L9_C "MPZ1608S601ATD25" 0603 4150,585 r270 top value="600 ohm" (schematic designator L9)
L9_D "MPZ1608S601ATD25" 0603 5600,585 r270 top value="600 ohm" (schematic designator L9)
L9_E "MPZ1608S601ATD25" 0603 7050,585 r270 top value="600 ohm" (schematic designator L9)
L9_F "MPZ1608S601ATD25" 0603 8500,585 r270 top value="600 ohm" (schematic designator L9)
LBL1 "THT-14-423-10" Label_650x200 650,2120 r180 top
Logo1 "Texas Instruments" TI_Stacked_Overlay_Small 755,2535 r0 top
Logo2 "CE Mark" CE_Mark_5mm 4270,2525 r0 top (schematic designator LOGO2)
Logo3 "FCC disclaimer" FCC_disclaimer 4755,2280 r0 top
Logo4 "WEEE logo" WEEE_Minimum 6385,2490 r0 top
NT_A1_A "Net-Tie" Net-Tie_10milWide_30milLong 465,1365 r180 bottom net-tie (schematic designator NT_A1)
NT_A1_B "Net-Tie" Net-Tie_10milWide_30milLong 1915,1365 r180 bottom net-tie (schematic designator NT_A1)
NT_A1_C "Net-Tie" Net-Tie_10milWide_30milLong 3365,1365 r180 bottom net-tie (schematic designator NT_A1)
NT_A1_D "Net-Tie" Net-Tie_10milWide_30milLong 4815,1365 r180 bottom net-tie (schematic designator NT_A1)
NT_A1_E "Net-Tie" Net-Tie_10milWide_30milLong 6265,1365 r180 bottom net-tie (schematic designator NT_A1)
NT_A1_F "Net-Tie" Net-Tie_10milWide_30milLong 7715,1365 r180 bottom net-tie (schematic designator NT_A1)
NT_B1_A "Net-Tie" Net-Tie_10milWide_30milLong 470,1005 r180 bottom net-tie (schematic designator NT_B1)
NT_B1_B "Net-Tie" Net-Tie_10milWide_30milLong 1920,1005 r180 bottom net-tie (schematic designator NT_B1)
NT_B1_C "Net-Tie" Net-Tie_10milWide_30milLong 3370,1005 r180 bottom net-tie (schematic designator NT_B1)
NT_B1_D "Net-Tie" Net-Tie_10milWide_30milLong 4820,1005 r180 bottom net-tie (schematic designator NT_B1)
NT_B1_E "Net-Tie" Net-Tie_10milWide_30milLong 6270,1005 r180 bottom net-tie (schematic designator NT_B1)
NT_B1_F "Net-Tie" Net-Tie_10milWide_30milLong 7720,1005 r180 bottom net-tie (schematic designator NT_B1)
NT_C1_A "Net-Tie" Net-Tie_10milWide_30milLong 1035,975 r0 bottom net-tie (schematic designator NT_C1)
NT_C1_B "Net-Tie" Net-Tie_10milWide_30milLong 2485,975 r0 bottom net-tie (schematic designator NT_C1)
NT_C1_C "Net-Tie" Net-Tie_10milWide_30milLong 3935,975 r0 bottom net-tie (schematic designator NT_C1)
NT_C1_D "Net-Tie" Net-Tie_10milWide_30milLong 5385,975 r0 bottom net-tie (schematic designator NT_C1)
NT_C1_E "Net-Tie" Net-Tie_10milWide_30milLong 6835,975 r0 bottom net-tie (schematic designator NT_C1)
NT_C1_F "Net-Tie" Net-Tie_10milWide_30milLong 8285,975 r0 bottom net-tie (schematic designator NT_C1)
NT_D1_A "Net-Tie" Net-Tie_10milWide_30milLong 1035,1325 r0 bottom net-tie (schematic designator NT_D1)
NT_D1_B "Net-Tie" Net-Tie_10milWide_30milLong 2485,1325 r0 bottom net-tie (schematic designator NT_D1)
NT_D1_C "Net-Tie" Net-Tie_10milWide_30milLong 3935,1325 r0 bottom net-tie (schematic designator NT_D1)
NT_D1_D "Net-Tie" Net-Tie_10milWide_30milLong 5385,1325 r0 bottom net-tie (schematic designator NT_D1)
NT_D1_E "Net-Tie" Net-Tie_10milWide_30milLong 6835,1325 r0 bottom net-tie (schematic designator NT_D1)
NT_D1_F "Net-Tie" Net-Tie_10milWide_30milLong 8285,1325 r0 bottom net-tie (schematic designator NT_D1)
Q1_A "CSD19538Q3A" DNH0008A_NV 270,1465 r180 top value=100V (schematic designator Q1)
Q1_B "CSD19538Q3A" DNH0008A_NV 1720,1465 r180 top value=100V (schematic designator Q1)
Q1_C "CSD19538Q3A" DNH0008A_NV 3170,1465 r180 top value=100V (schematic designator Q1)
Q1_D "CSD19538Q3A" DNH0008A_NV 4620,1465 r180 top value=100V (schematic designator Q1)
Q1_E "CSD19538Q3A" DNH0008A_NV 6070,1465 r180 top value=100V (schematic designator Q1)
Q1_F "CSD19538Q3A" DNH0008A_NV 7520,1465 r180 top value=100V (schematic designator Q1)
Q2_A "CSD19538Q3A" DNH0008A_NV 270,1285 r180 top value=100V (schematic designator Q2)
Q2_B "CSD19538Q3A" DNH0008A_NV 1720,1285 r180 top value=100V (schematic designator Q2)
Q2_C "CSD19538Q3A" DNH0008A_NV 3170,1285 r180 top value=100V (schematic designator Q2)
Q2_D "CSD19538Q3A" DNH0008A_NV 4620,1285 r180 top value=100V (schematic designator Q2)
Q2_E "CSD19538Q3A" DNH0008A_NV 6070,1285 r180 top value=100V (schematic designator Q2)
Q2_F "CSD19538Q3A" DNH0008A_NV 7520,1285 r180 top value=100V (schematic designator Q2)
Q3_A "CSD19538Q3A" DNH0008A_NV 1235,875 r0 top value=100V (schematic designator Q3)
Q3_B "CSD19538Q3A" DNH0008A_NV 2685,875 r0 top value=100V (schematic designator Q3)
Q3_C "CSD19538Q3A" DNH0008A_NV 4135,875 r0 top value=100V (schematic designator Q3)
Q3_D "CSD19538Q3A" DNH0008A_NV 5585,875 r0 top value=100V (schematic designator Q3)
Q3_E "CSD19538Q3A" DNH0008A_NV 7035,875 r0 top value=100V (schematic designator Q3)
Q3_F "CSD19538Q3A" DNH0008A_NV 8485,875 r0 top value=100V (schematic designator Q3)
Q4_A "CSD19538Q3A" DNH0008A_NV 1235,1055 r0 top value=100V (schematic designator Q4)
Q4_B "CSD19538Q3A" DNH0008A_NV 2685,1055 r0 top value=100V (schematic designator Q4)
Q4_C "CSD19538Q3A" DNH0008A_NV 4135,1055 r0 top value=100V (schematic designator Q4)
Q4_D "CSD19538Q3A" DNH0008A_NV 5585,1055 r0 top value=100V (schematic designator Q4)
Q4_E "CSD19538Q3A" DNH0008A_NV 7035,1055 r0 top value=100V (schematic designator Q4)
Q4_F "CSD19538Q3A" DNH0008A_NV 8485,1055 r0 top value=100V (schematic designator Q4)
Q5_A "CSD19538Q3A" DNH0008A_NV 270,1105 r180 top value=100V (schematic designator Q5)
Q5_B "CSD19538Q3A" DNH0008A_NV 1720,1105 r180 top value=100V (schematic designator Q5)
Q5_C "CSD19538Q3A" DNH0008A_NV 3170,1105 r180 top value=100V (schematic designator Q5)
Q5_D "CSD19538Q3A" DNH0008A_NV 4620,1105 r180 top value=100V (schematic designator Q5)
Q5_E "CSD19538Q3A" DNH0008A_NV 6070,1105 r180 top value=100V (schematic designator Q5)
Q5_F "CSD19538Q3A" DNH0008A_NV 7520,1105 r180 top value=100V (schematic designator Q5)
Q6_A "CSD19538Q3A" DNH0008A_NV 270,925 r180 top value=100V (schematic designator Q6)
Q6_B "CSD19538Q3A" DNH0008A_NV 1720,925 r180 top value=100V (schematic designator Q6)
Q6_C "CSD19538Q3A" DNH0008A_NV 3170,925 r180 top value=100V (schematic designator Q6)
Q6_D "CSD19538Q3A" DNH0008A_NV 4620,925 r180 top value=100V (schematic designator Q6)
Q6_E "CSD19538Q3A" DNH0008A_NV 6070,925 r180 top value=100V (schematic designator Q6)
Q6_F "CSD19538Q3A" DNH0008A_NV 7520,925 r180 top value=100V (schematic designator Q6)
Q7_A "CSD19538Q3A" DNH0008A_NV 1235,1245 r0 top value=100V (schematic designator Q7)
Q7_B "CSD19538Q3A" DNH0008A_NV 2685,1245 r0 top value=100V (schematic designator Q7)
Q7_C "CSD19538Q3A" DNH0008A_NV 4135,1245 r0 top value=100V (schematic designator Q7)
Q7_D "CSD19538Q3A" DNH0008A_NV 5585,1245 r0 top value=100V (schematic designator Q7)
Q7_E "CSD19538Q3A" DNH0008A_NV 7035,1245 r0 top value=100V (schematic designator Q7)
Q7_F "CSD19538Q3A" DNH0008A_NV 8485,1245 r0 top value=100V (schematic designator Q7)
Q8_A "CSD19538Q3A" DNH0008A_NV 1235,1435 r0 top value=100V (schematic designator Q8)
Q8_B "CSD19538Q3A" DNH0008A_NV 2685,1435 r0 top value=100V (schematic designator Q8)
Q8_C "CSD19538Q3A" DNH0008A_NV 4135,1435 r0 top value=100V (schematic designator Q8)
Q8_D "CSD19538Q3A" DNH0008A_NV 5585,1435 r0 top value=100V (schematic designator Q8)
Q8_E "CSD19538Q3A" DNH0008A_NV 7035,1435 r0 top value=100V (schematic designator Q8)
Q8_F "CSD19538Q3A" DNH0008A_NV 8485,1435 r0 top value=100V (schematic designator Q8)
R1 "CRCW0402150KFKED" 0402 2673.31,2095 r0 top value=150k
R2 "CRCW0402100KFKED" 0402 2673.31,2150 r0 top value=100k
R3 "CRCW040210K0FKED" 0402 3063.31,2035 r180 top value=10.0k
R4 "CRCW0402133KFKED" 0402 3228.31,2205 r270 top value=133k
R5 "CRCW04023K92FKED" 0402 2673.31,2205 r180 top value=3.92k
R6 "CRCW04026K04FKED" 0402 2953.31,2090 r180 top value=6.04k
R7 "RC0603JR-070RL" 0603 2998.31,2510 r270 top value=0
R8 "CRCW04024K70JNED" 0402 8145,2050 r90 top value=4.7k
R9 "CRCW040210K0FKED" 0402 7610,2340 r180 top value=10.0k
R10 "CRCW040210K0FKED" 0402 7405,2340 r180 top value=10.0k
R11 "CRCW04024K70JNED" 0402 7104.69,2050 r0 top value=4.7k
R12 "CRCW04024K70JNED" 0402 6994.69,2050 r180 top value=4.7k
R13_A "ERJ-2GE0R00X" 0402 800,1490 r90 top value=0 (schematic designator R13)
R13_B "ERJ-2GE0R00X" 0402 2250,1490 r90 top value=0 (schematic designator R13)
R13_C "ERJ-2GE0R00X" 0402 3700,1490 r90 top value=0 (schematic designator R13)
R13_D "ERJ-2GE0R00X" 0402 5150,1490 r90 top value=0 (schematic designator R13)
R13_E "ERJ-2GE0R00X" 0402 6600,1490 r90 top value=0 (schematic designator R13)
R13_F "ERJ-2GE0R00X" 0402 8050,1490 r90 top value=0 (schematic designator R13)
R14_A "ERJ-2GE0R00X" 0402 745,1490 r90 top value=0 (schematic designator R14)
R14_B "ERJ-2GE0R00X" 0402 2195,1490 r90 top value=0 (schematic designator R14)
R14_C "ERJ-2GE0R00X" 0402 3645,1490 r90 top value=0 (schematic designator R14)
R14_D "ERJ-2GE0R00X" 0402 5095,1490 r90 top value=0 (schematic designator R14)
R14_E "ERJ-2GE0R00X" 0402 6545,1490 r90 top value=0 (schematic designator R14)
R14_F "ERJ-2GE0R00X" 0402 7995,1490 r90 top value=0 (schematic designator R14)
R15_A "CRM0805-FX-R510ELF" 0805L 370,1495 r0 bottom value=0.51 (schematic designator R15)
R15_B "CRM0805-FX-R510ELF" 0805L 1820,1495 r0 bottom value=0.51 (schematic designator R15)
R15_C "CRM0805-FX-R510ELF" 0805L 3270,1495 r0 bottom value=0.51 (schematic designator R15)
R15_D "CRM0805-FX-R510ELF" 0805L 4720,1495 r0 bottom value=0.51 (schematic designator R15)
R15_E "CRM0805-FX-R510ELF" 0805L 6170,1495 r0 bottom value=0.51 (schematic designator R15)
R15_F "CRM0805-FX-R510ELF" 0805L 7620,1495 r0 bottom value=0.51 (schematic designator R15)
R16_A "CRM0805-FX-R510ELF" 0805L 370,1420 r0 bottom value=0.51 (schematic designator R16)
R16_B "CRM0805-FX-R510ELF" 0805L 1820,1420 r0 bottom value=0.51 (schematic designator R16)
R16_C "CRM0805-FX-R510ELF" 0805L 3270,1420 r0 bottom value=0.51 (schematic designator R16)
R16_D "CRM0805-FX-R510ELF" 0805L 4720,1420 r0 bottom value=0.51 (schematic designator R16)
R16_E "CRM0805-FX-R510ELF" 0805L 6170,1420 r0 bottom value=0.51 (schematic designator R16)
R16_F "CRM0805-FX-R510ELF" 0805L 7620,1420 r0 bottom value=0.51 (schematic designator R16)
R17_A "CRM0805-FX-R510ELF" 0805L 370,1310 r0 bottom value=0.51 (schematic designator R17)
R17_B "CRM0805-FX-R510ELF" 0805L 1820,1310 r0 bottom value=0.51 (schematic designator R17)
R17_C "CRM0805-FX-R510ELF" 0805L 3270,1310 r0 bottom value=0.51 (schematic designator R17)
R17_D "CRM0805-FX-R510ELF" 0805L 4720,1310 r0 bottom value=0.51 (schematic designator R17)
R17_E "CRM0805-FX-R510ELF" 0805L 6170,1310 r0 bottom value=0.51 (schematic designator R17)
R17_F "CRM0805-FX-R510ELF" 0805L 7620,1310 r0 bottom value=0.51 (schematic designator R17)
R18_A "CRM0805-FX-R510ELF" 0805L 370,1230 r0 bottom value=0.51 (schematic designator R18)
R18_B "CRM0805-FX-R510ELF" 0805L 1820,1230 r0 bottom value=0.51 (schematic designator R18)
R18_C "CRM0805-FX-R510ELF" 0805L 3270,1230 r0 bottom value=0.51 (schematic designator R18)
R18_D "CRM0805-FX-R510ELF" 0805L 4720,1230 r0 bottom value=0.51 (schematic designator R18)
R18_E "CRM0805-FX-R510ELF" 0805L 6170,1230 r0 bottom value=0.51 (schematic designator R18)
R18_F "CRM0805-FX-R510ELF" 0805L 7620,1230 r0 bottom value=0.51 (schematic designator R18)
R19_A "CRM0805-FX-R510ELF" 0805L 1135,850 r180 bottom value=0.51 (schematic designator R19)
R19_B "CRM0805-FX-R510ELF" 0805L 2585,850 r180 bottom value=0.51 (schematic designator R19)
R19_C "CRM0805-FX-R510ELF" 0805L 4035,850 r180 bottom value=0.51 (schematic designator R19)
R19_D "CRM0805-FX-R510ELF" 0805L 5485,850 r180 bottom value=0.51 (schematic designator R19)
R19_E "CRM0805-FX-R510ELF" 0805L 6935,850 r180 bottom value=0.51 (schematic designator R19)
R19_F "CRM0805-FX-R510ELF" 0805L 8385,850 r180 bottom value=0.51 (schematic designator R19)
R20_A "CRM0805-FX-R510ELF" 0805L 1135,925 r180 bottom value=0.51 (schematic designator R20)
R20_B "CRM0805-FX-R510ELF" 0805L 2585,925 r180 bottom value=0.51 (schematic designator R20)
R20_C "CRM0805-FX-R510ELF" 0805L 4035,925 r180 bottom value=0.51 (schematic designator R20)
R20_D "CRM0805-FX-R510ELF" 0805L 5485,925 r180 bottom value=0.51 (schematic designator R20)
R20_E "CRM0805-FX-R510ELF" 0805L 6935,925 r180 bottom value=0.51 (schematic designator R20)
R20_F "CRM0805-FX-R510ELF" 0805L 8385,925 r180 bottom value=0.51 (schematic designator R20)
R21_A "CRM0805-FX-R510ELF" 0805L 1135,1025 r180 bottom value=0.51 (schematic designator R21)
R21_B "CRM0805-FX-R510ELF" 0805L 2585,1025 r180 bottom value=0.51 (schematic designator R21)
R21_C "CRM0805-FX-R510ELF" 0805L 4035,1025 r180 bottom value=0.51 (schematic designator R21)
R21_D "CRM0805-FX-R510ELF" 0805L 5485,1025 r180 bottom value=0.51 (schematic designator R21)
R21_E "CRM0805-FX-R510ELF" 0805L 6935,1025 r180 bottom value=0.51 (schematic designator R21)
R21_F "CRM0805-FX-R510ELF" 0805L 8385,1025 r180 bottom value=0.51 (schematic designator R21)
R22_A "CRM0805-FX-R510ELF" 0805L 1135,1100 r180 bottom value=0.51 (schematic designator R22)
R22_B "CRM0805-FX-R510ELF" 0805L 2585,1100 r180 bottom value=0.51 (schematic designator R22)
R22_C "CRM0805-FX-R510ELF" 0805L 4035,1100 r180 bottom value=0.51 (schematic designator R22)
R22_D "CRM0805-FX-R510ELF" 0805L 5485,1100 r180 bottom value=0.51 (schematic designator R22)
R22_E "CRM0805-FX-R510ELF" 0805L 6935,1100 r180 bottom value=0.51 (schematic designator R22)
R22_F "CRM0805-FX-R510ELF" 0805L 8385,1100 r180 bottom value=0.51 (schematic designator R22)
R23_A "CRM0805-FX-R510ELF" 0805L 370,1135 r0 bottom value=0.51 (schematic designator R23)
R23_B "CRM0805-FX-R510ELF" 0805L 1820,1135 r0 bottom value=0.51 (schematic designator R23)
R23_C "CRM0805-FX-R510ELF" 0805L 3270,1135 r0 bottom value=0.51 (schematic designator R23)
R23_D "CRM0805-FX-R510ELF" 0805L 4720,1135 r0 bottom value=0.51 (schematic designator R23)
R23_E "CRM0805-FX-R510ELF" 0805L 6170,1135 r0 bottom value=0.51 (schematic designator R23)
R23_F "CRM0805-FX-R510ELF" 0805L 7620,1135 r0 bottom value=0.51 (schematic designator R23)
R24_A "CRM0805-FX-R510ELF" 0805L 370,1055 r0 bottom value=0.51 (schematic designator R24)
R24_B "CRM0805-FX-R510ELF" 0805L 1820,1055 r0 bottom value=0.51 (schematic designator R24)
R24_C "CRM0805-FX-R510ELF" 0805L 3270,1055 r0 bottom value=0.51 (schematic designator R24)
R24_D "CRM0805-FX-R510ELF" 0805L 4720,1055 r0 bottom value=0.51 (schematic designator R24)
R24_E "CRM0805-FX-R510ELF" 0805L 6170,1055 r0 bottom value=0.51 (schematic designator R24)
R24_F "CRM0805-FX-R510ELF" 0805L 7620,1055 r0 bottom value=0.51 (schematic designator R24)
R25_A "CRM0805-FX-R510ELF" 0805L 370,955 r0 bottom value=0.51 (schematic designator R25)
R25_B "CRM0805-FX-R510ELF" 0805L 1820,955 r0 bottom value=0.51 (schematic designator R25)
R25_C "CRM0805-FX-R510ELF" 0805L 3270,955 r0 bottom value=0.51 (schematic designator R25)
R25_D "CRM0805-FX-R510ELF" 0805L 4720,955 r0 bottom value=0.51 (schematic designator R25)
R25_E "CRM0805-FX-R510ELF" 0805L 6170,955 r0 bottom value=0.51 (schematic designator R25)
R25_F "CRM0805-FX-R510ELF" 0805L 7620,955 r0 bottom value=0.51 (schematic designator R25)
R26_A "CRM0805-FX-R510ELF" 0805L 370,875 r0 bottom value=0.51 (schematic designator R26)
R26_B "CRM0805-FX-R510ELF" 0805L 1820,875 r0 bottom value=0.51 (schematic designator R26)
R26_C "CRM0805-FX-R510ELF" 0805L 3270,875 r0 bottom value=0.51 (schematic designator R26)
R26_D "CRM0805-FX-R510ELF" 0805L 4720,875 r0 bottom value=0.51 (schematic designator R26)
R26_E "CRM0805-FX-R510ELF" 0805L 6170,875 r0 bottom value=0.51 (schematic designator R26)
R26_F "CRM0805-FX-R510ELF" 0805L 7620,875 r0 bottom value=0.51 (schematic designator R26)
R27_A "CRM0805-FX-R510ELF" 0805L 1135,1200 r180 bottom value=0.51 (schematic designator R27)
R27_B "CRM0805-FX-R510ELF" 0805L 2585,1200 r180 bottom value=0.51 (schematic designator R27)
R27_C "CRM0805-FX-R510ELF" 0805L 4035,1200 r180 bottom value=0.51 (schematic designator R27)
R27_D "CRM0805-FX-R510ELF" 0805L 5485,1200 r180 bottom value=0.51 (schematic designator R27)
R27_E "CRM0805-FX-R510ELF" 0805L 6935,1200 r180 bottom value=0.51 (schematic designator R27)
R27_F "CRM0805-FX-R510ELF" 0805L 8385,1200 r180 bottom value=0.51 (schematic designator R27)
R28_A "CRM0805-FX-R510ELF" 0805L 1135,1275 r180 bottom value=0.51 (schematic designator R28)
R28_B "CRM0805-FX-R510ELF" 0805L 2585,1275 r180 bottom value=0.51 (schematic designator R28)
R28_C "CRM0805-FX-R510ELF" 0805L 4035,1275 r180 bottom value=0.51 (schematic designator R28)
R28_D "CRM0805-FX-R510ELF" 0805L 5485,1275 r180 bottom value=0.51 (schematic designator R28)
R28_E "CRM0805-FX-R510ELF" 0805L 6935,1275 r180 bottom value=0.51 (schematic designator R28)
R28_F "CRM0805-FX-R510ELF" 0805L 8385,1275 r180 bottom value=0.51 (schematic designator R28)
R29_A "CRM0805-FX-R510ELF" 0805L 1135,1385 r180 bottom value=0.51 (schematic designator R29)
R29_B "CRM0805-FX-R510ELF" 0805L 2585,1385 r180 bottom value=0.51 (schematic designator R29)
R29_C "CRM0805-FX-R510ELF" 0805L 4035,1385 r180 bottom value=0.51 (schematic designator R29)
R29_D "CRM0805-FX-R510ELF" 0805L 5485,1385 r180 bottom value=0.51 (schematic designator R29)
R29_E "CRM0805-FX-R510ELF" 0805L 6935,1385 r180 bottom value=0.51 (schematic designator R29)
R29_F "CRM0805-FX-R510ELF" 0805L 8385,1385 r180 bottom value=0.51 (schematic designator R29)
R30_A "CRM0805-FX-R510ELF" 0805L 1135,1460 r180 bottom value=0.51 (schematic designator R30)
R30_B "CRM0805-FX-R510ELF" 0805L 2585,1460 r180 bottom value=0.51 (schematic designator R30)
R30_C "CRM0805-FX-R510ELF" 0805L 4035,1460 r180 bottom value=0.51 (schematic designator R30)
R30_D "CRM0805-FX-R510ELF" 0805L 5485,1460 r180 bottom value=0.51 (schematic designator R30)
R30_E "CRM0805-FX-R510ELF" 0805L 6935,1460 r180 bottom value=0.51 (schematic designator R30)
R30_F "CRM0805-FX-R510ELF" 0805L 8385,1460 r180 bottom value=0.51 (schematic designator R30)
R31 "CRCW04024K70JNED" 0402 7780,2435 r180 top value=4.7k
R32 "CRCW04024K70JNED" 0402 7835,2055 r0 top value=4.7k
R33 "CRCW040210K0FKED" 0402 7104.69,2405 r180 top value=10.0k
R34 "CRCW040210K0FKED" 0402 6994.69,2405 r0 top value=10.0k
R35_A "ERJ-2GE0R00X" 0402 690,1490 r90 top value=0 (schematic designator R35)
R35_B "ERJ-2GE0R00X" 0402 2140,1490 r90 top value=0 (schematic designator R35)
R35_C "ERJ-2GE0R00X" 0402 3590,1490 r90 top value=0 (schematic designator R35)
R35_D "ERJ-2GE0R00X" 0402 5040,1490 r90 top value=0 (schematic designator R35)
R35_E "ERJ-2GE0R00X" 0402 6490,1490 r90 top value=0 (schematic designator R35)
R35_F "ERJ-2GE0R00X" 0402 7940,1490 r90 top value=0 (schematic designator R35)
R36 "ERJ-2GE0R00X" 0402 7985,2500 r270 top value=0
R37 "ERJ-2GE0R00X" 0402 7930,2500 r270 top value=0
R38 "ERJ-2GE0R00X" 0402 7920,1980 r270 top value=0
SH-J1 "SPC02SYAN" SPC02SYAN 8550,1800 r180 top value=1x2
TP1 "VPWR" Keystone5000 2050,2250 r90 top
TP2 "PSE_3.3V" Keystone5000 3850,2500 r90 top
TP3 "GND" Keystone5001 1450,2250 r90 top
TP4 "GND" Keystone5001 3850,2250 r90 top
TP5 "RESET" Keystone5003 8300,2500 r90 top
TP6 "OSS" Keystone5003 8450,2500 r90 top
TP7 "INT" Keystone5003 8600,2500 r90 top
TP8 "SCL" Keystone5003 8600,2100 r90 top
TP9 "SDA" Keystone5003 8600,2300 r90 top
TP10 "3.3V_ISO" Keystone5000 8300,2300 r90 top
TP11 "PSE_RST" Keystone5002 5850.23,2500.35 r90 top
TP12 "PSE_OSS" Keystone5002 4850,2500 r90 top
TP13 "PSE_INT" Keystone5002 5600.23,2500.35 r90 top
TP14 "GND" Keystone5001 6100.12,2500.18 r90 top
TP15 "GND_ISO" Keystone5001 8450,2300 r90 top
TP16 "PSE_SDA" Keystone5002 5100.12,2500.18 r90 top
TP17 "PSE_SCL" Keystone5002 5350,2500 r90 top
TP18 "GND" Keystone5001 4600.12,2500.18 r90 top
U1 "LM5017MRX/NOPB" DDA0008B_N 2888.31,2230 r0 top
U2 "ISO7731FDBQ" DBQ0016A_N 7935,2235 r270 top
U3 "ISO1541DR" D0008B_L 7049.69,2235 r270 top
U4_A "TPS23880RTQR" RTQ0056E 750,1155 r0 top (schematic designator U4)
U4_B "TPS23880RTQR" RTQ0056E 2200,1155 r0 top (schematic designator U4)
U4_C "TPS23880RTQR" RTQ0056E 3650,1155 r0 top (schematic designator U4)
U4_D "TPS23880RTQR" RTQ0056E 5100,1155 r0 top (schematic designator U4)
U4_E "TPS23880RTQR" RTQ0056E 6550,1155 r0 top (schematic designator U4)
U4_F "TPS23880RTQR" RTQ0056E 8000,1155 r0 top (schematic designator U4)
ZZ1 "This Assembly Note is for PCB labels only" AssemblyNoteLabel 200,4540 r0 top
ZZ2 "These assemblies are ESD sensitive, ESD precautions shall be observed." AssemblyNote 185,4365 r0 top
